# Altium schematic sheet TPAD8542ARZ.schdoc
size 127 x 101 mm
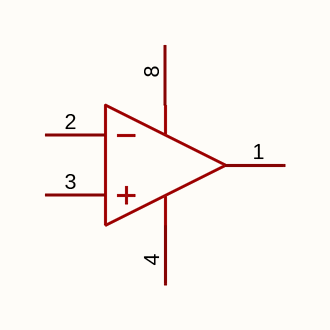
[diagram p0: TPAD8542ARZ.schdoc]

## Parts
U?  tpad8542arz  [SOIC-8_L5.0-W4.0-P1.27-LS6.0-BL]  (value not drawn)  (part A of 2)

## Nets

Not connected (* = marked no-connect by the designer): U? 1(OUT1) 2(IN1-) 3(IN1+) 4(VEE) 8(VCC)

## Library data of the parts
U? = tpad8542arz: 放大器数:2;轨到轨:轨到轨输入,轨到轨输出;增益带宽积(GBW):1MHz;输入失调电压(Vos):5mV;压摆率(SR):-;输入偏置电流(Ib):10pA;; Manufacturer: TECH PUBLIC(台舟); AddInBom: yes; ModelId: 7abc64c95a1a4a04a4ef38f9097c870b; ModelTransform: 192.913,236.22,0,0,0,0,0,0,0; Number of Channels: 2; Gain Bandwidth Product: 1MHz; Vos - Input Offset Voltage: 5mV; Input Offset Voltage Drift(Vos TC): 650nV/℃; Ib - Input Bias Current: 10pA; Common Mode Rejection Ratio(CMRR): 85dB; Quiescent Current: 40uA; Output Current: 20mA; Single supply: 2.2V~5.5V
